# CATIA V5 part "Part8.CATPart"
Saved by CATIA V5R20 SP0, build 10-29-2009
Part number: Part8
Bounding box of the stored display mesh (mm): x -400 to 0, y -400 to 400, z -400 to 400
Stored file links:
  E:\新建文件夹 (2)\Part8.CATPart
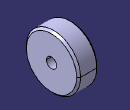
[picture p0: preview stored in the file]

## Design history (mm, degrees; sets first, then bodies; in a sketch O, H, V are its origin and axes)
Body1 (main body)
  Sketch1 on yz-plane, origin (0, 0, 0), H (0, 1, 0), V (0, 0, 1)
    circle A1 centre (0, 0) radius 400
  Pad1: profile Sketch1, direction (-1, 0, 0), length 300
  Sketch2 on end face of Pad1, origin (-300, 0, 0), H (0, -1, 0), V (0, 0, 1)
    circle A1 centre (0, 0) radius 300
    point P1 (0, 300)
    point P2 (300, 0)
    coincidence: A1 P1, P1 V, P2 A1, P2 H
  Plane1: type Normal, Curve Sketch2.A1, RefPoint Sketch2.P2
  Sketch3 on Plane1, origin (0, 0, 0), H (1, 0, 0), V (0, 1, 0)
    circle A1 centre (-300, -300) radius 20
    point P1 (-300, -300)
    reference projected point E1 (-300, -300) from Sketch2.P2
    radius A1 = 20
    coincidence: E1 P1
  Chamfer1: length 30, angle 45, on face of Pad1 from Sketch1.A1
  Shaft1: profile Sketch3, axis X axis, angle 360
  Sketch4 on end face of Pad1, origin (-300, 0, 0), H (0, -1, 0), V (0, 0, 1)
    circle A1 centre (0, 0) radius 150
    point P1 (0, 150)
    coincidence: A1 P1, P1 V
  Plane2: type Offset, RefPlane yz-plane, Offset 400, reversed
  Sketch5 on Plane2, origin (-400, 0, 0), H (0, 1, 0), V (0, 0, 1)
    circle A1 centre (0, 0) radius 75
    point P1 (0, 75)
    coincidence: A1 P1, P1 V
  Loft1: solid, Sections (Sketch5; Sketch4)
  Body2
    Sketch6 on yz-plane, origin (0, 0, 0), H (0, 1, 0), V (0, 0, 1)
      circle A1 centre (0, 0) radius 75
      point P1 (0, 75)
      coincidence: A1 P1, P1 V
    Pad2: profile Sketch6, direction (-1, 0, 0), length 400
  Remove1: tool Body2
